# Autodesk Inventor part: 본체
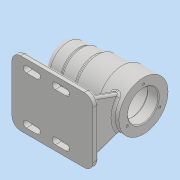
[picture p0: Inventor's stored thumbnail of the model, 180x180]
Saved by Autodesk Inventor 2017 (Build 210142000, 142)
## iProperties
Part Number: 본체
Material: 일반
Document SubType Name: Modeling
Designer: MRC
Density: 1 g/cm^3
Appearance: 기본값
Author: MRC
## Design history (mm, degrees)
sketch "스케치1"
  geometry: L1 (-56, 0)-(56, 0); L2 (-56, 0)-(-56, 25); L3 (-56, 25)-(-32, 25); L4 (-32, 25)-(-32, 27); L5 (-32, 27)-(-10, 27); L6 (-10, 27)-(-10, 30); L7 (-10, 30)-(24, 30); L8 (24, 30)-(24, 34); L9 (24, 34)-(56, 34); L10 (56, 34)-(56, 0); L11 (56, 21)-(41, 21); L12 (41, 21)-(41, 24); L13 (41, 24)-(-13, 24); L14 (-13, 24)-(-13, 21); L15 (-13, 21)-(-25, 21); L16 (-25, 21)-(-25, 17.5); L17 (-25, 17.5)-(-43, 17.5); L18 (-43, 17.5)-(-43, 16); L19 (-43, 16)-(-47, 16); L20 (-47, 16)-(-47, 10.5); L21 (-47, 10.5)-(-50, 10.5); L22 (-50, 10.5)-(-50, 0); 2 further points
  constraints: 44 end point, 20 perpendicular, 2 point on line, 1 coincident, 1 horizontal, 1 midpoint, 1 vertical
  dimensions: "d0" = 112 distance of L1.start L1.end; "d1" = 50 diameter of L3 L1; "d2" = 54 diameter of L5 L1; "d3" = 60 diameter of L7 L1; "d4" = 68 diameter of L9 L1; "d5" = 24 distance of L2.end L3.end; "d6" = 46 distance between parallel lines of L6 L2; "d7" = 80 distance between parallel lines of L8 L2; "d8" = 42 diameter of L11 L1; "d9" = 48 diameter of L13 L1; "d10" = 42 diameter of L15 L1; "d11" = 21 diameter of L21 L1; "d12" = 32 diameter of L19 L1; "d13" = 35 diameter of L17 L1; "d14" = 15 distance of L11.start L11.end; "d15" = 54 distance of L12.end L13.end; "d16" = 12 distance of L14.end L15.end; "d17" = 18 distance of L16.end L17.end; "d18" = 4 distance of L18.end L19.end; "d19" = 3 distance of L20.end L21.end
revolve "회전1" sketch "스케치1" stored, may be unused: angle "d20" = 90 deg
fillet "모깎기1" dims "d21" = 0.3
fillet "모깎기2" dims "d22" = 3
chamfer "모따기1" distance "d23" = 1; stored, may be unused: second distance "d24" = 2, angle "d25" = 45 deg
fillet "모깎기3" dims "d26" = 8
fillet "모깎기4" dims "d27" = 3
sketch "스케치2"
  geometry: C1 r 34 at (0, 0) reference; 1 further point
  constraints: 1 horizontal alignment
  dimensions: "d28" = 26 distance of point (-26, 0) C1.centre
hole "구멍1" sketch "스케치2" at (-26, 0) diameter "d29" = 3.242; stored, may be unused: countersink angle "d33" = 90 deg, drill point angle "d35" = 118 deg; dims "d30" = 8, "d31" = 4, "d32" = 2, "d34" = 11
sketch "스케치3"
  geometry: L1 (-56, -62)-(56, -62); L2 (56, -62)-(56, -70); L3 (56, -70)-(-56, -70); L4 (-56, -70)-(-56, -62); 2 further points
  constraints: 8 end point, 2 parallel, 1 horizontal, 1 midpoint, 1 perpendicular, 1 vertical alignment
  dimensions: "d39" = 112 distance of L2.end L3.end; "d40" = 8 distance of L1.end L2.end; "d41" = 70 distance from line of point (0, 0) L3
extrude "돌출1" join sketch "스케치3" stored distance "d42" = 90; taper "d43" = 0 deg
node "작업 평면1"
sketch "스케치4"
  geometry: L1 (21.591, 45.342)-(8, 8); L2 (0, 8)-(0, 0) reference; L3 (90, 8)-(0, 8) reference; L4 (68.409, 45.342)-(82, 8); L5 (90, 0)-(90, 8) reference; A1 r 34 centre (45, 70) between (68.409, 45.342) and (21.591, 45.342) reference; 1 further point
  constraints: 4 end point, 2 point on circle, 2 point on line
  dimensions: "d45" = 8 distance from line of L1.end L2; "d46" = 110 deg angle of L1 L3; "d47" = 8 distance from line of L4.end L5; "d48" = 110 deg angle of L4 L3
extrude "돌출2" join sketch "스케치4" distance "d49" = 8; taper "d50" = 0 deg
sketch "스케치5"
  geometry: L1 (-29, -62)-(-24.783, -46.262); L2 (56, -62)-(-56, -62) reference; L3 (48, -24.658)-(48, -62) reference; 1 further point
  constraints: 2 end point, 1 point on line
  dimensions: "d51" = 105 deg angle of L1 L2; "d53" = 77 distance from line of L3 L1.start
feature "리브1" sketch "스케치5" dims "d54" = 1, "d55" = 8, "d56" = 0, "d57" = 0, "d58" = 1, "d59" = 1
sketch "스케치6" dims "d3" = 60
  geometry: L1 (0, 0)-(0, -90) reference; L2 (20, -78)-(35, -78); L3 (20, -82.5)-(35, -82.5); L4 (35, -73.5)-(20, -73.5); L5 (60, -78)-(75, -78); L6 (60, -82.5)-(75, -82.5); L7 (75, -73.5)-(60, -73.5); A1 r 4.5 centre (20, -78) between (20, -73.5) and (20, -82.5); A2 r 4.5 centre (35, -78) between (35, -82.5) and (35, -73.5); A3 r 4.5 centre (60, -78) between (60, -73.5) and (60, -82.5); A4 r 4.5 centre (75, -78) between (75, -82.5) and (75, -73.5); 3 further points
  constraints: 16 end point, 8 point on circle, 8 tangent, 4 centre point, 2 midpoint, 2 parallel, 2 point on line, 1 horizontal
  dimensions: "d60" = 20 distance from line of L2.start L1; "d61" = 15 distance of L2.start L2.end; "d62" = 25 distance of L5.start L2.end; "d63" = 15 distance of L5.start L5.end; "d64" = 9 distance between parallel lines of L4 L3; "d65" = 33 distance from line of L2 point (56, -45); "d66" = 9 distance between parallel lines of L6 L7
extrude "돌출3" cut sketch "스케치6" stored distance "d67" = 8; taper "d68" = 0 deg
sketch "스케치7"
  geometry: L1 (0, 0)-(0, -90) reference; 2 further points
  constraints: 1 horizontal alignment, 1 other
  dimensions: "d69" = 12 distance from line of point (12, -45) L1
feature "엠보싱1" sketch "스케치7" dims "d14" = 15, "d70" = 0.5, "d71" = 0
fillet "모깎기5" dims "d72" = 12
fillet "모깎기6" dims "d73" = 3
fillet "모깎기7" dims "d74" = 3
fillet "모깎기8" dims "d75" = 3
fillet "모깎기9" dims "d76" = 3
node "솔리드1"
pattern_circular "원형 패턴1" dims angle "d37" = 360 deg
mirror "미러1"
other parameters: "d44" = -8
